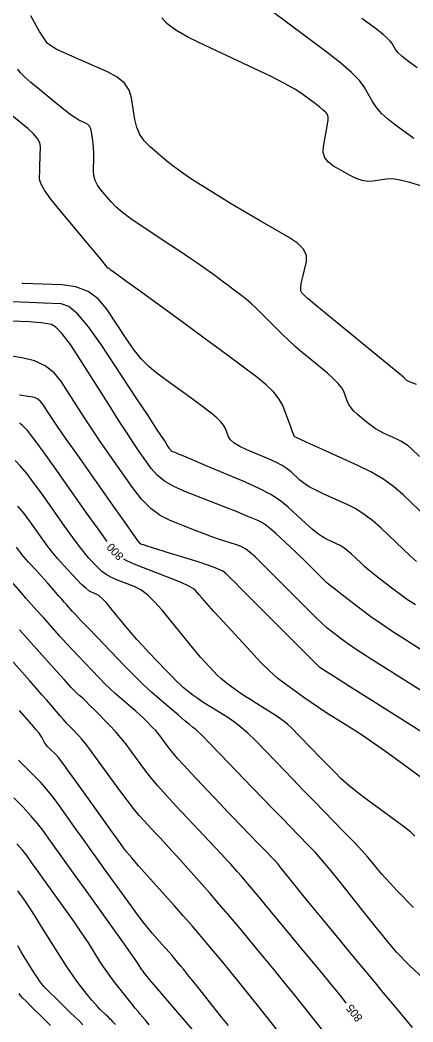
# Model space of a CAD drawing. Extents: x 2082232 to 2083549, y 592624 to 593832.
# Drawn here: x 2082379.6 to 2082413.2, y 593225.4 to 593311.1 of the extents above; entities that cross this region are included whole.
import ezdxf

# ---------------------------------------------------------------- set-up
doc = ezdxf.new("R2010")
doc.units = 0
doc.layers.add('DT_X_Contour_Major', color=7, linetype='Continuous')
doc.layers.add('DT_X_Contour_Minor', color=7, linetype='Continuous')

msp = doc.modelspace()

# ---------------------------------------------------------------- linework, layer by layer
at = {"layer": 'DT_X_Contour_Major'}
for points in [[(2082413.299, 593300.988), (2082411.619, 593302.197), (2082411.032, 593302.655), (2082410.532, 593303.123), (2082410.12, 593303.6), (2082409.794, 593304.087), (2082409.042, 593305.398), (2082408.633, 593305.95), (2082407.967, 593306.623), (2082407.047, 593307.418), (2082405.871, 593308.333), (2082402.394, 593310.936), (2082401.153, 593311.846)], [(2082413.526, 593264.794), (2082413.013, 593265.267), (2082412.371, 593265.872), (2082410.486, 593267.66), (2082409.774, 593268.288), (2082409.053, 593268.833), (2082408.322, 593269.295), (2082407.582, 593269.673), (2082405.597, 593270.569), (2082404.91, 593270.896), (2082404.339, 593271.204), (2082403.883, 593271.495), (2082403.542, 593271.767), (2082402.788, 593272.469), (2082402.454, 593272.736), (2082402.019, 593273.01), (2082401.483, 593273.29), (2082400.845, 593273.577), (2082399.009, 593274.352), (2082398.394, 593274.64), (2082397.926, 593274.922), (2082397.604, 593275.2), (2082397.43, 593275.472), (2082397.159, 593276.191), (2082397.015, 593276.469), (2082396.786, 593276.762), (2082396.471, 593277.071), (2082396.071, 593277.395), (2082394.889, 593278.281), (2082394.426, 593278.626), (2082393.925, 593278.996), (2082393.385, 593279.392), (2082392.806, 593279.813), (2082391.21, 593280.969), (2082390.606, 593281.471), (2082389.99, 593282.108), (2082389.363, 593282.881), (2082388.723, 593283.79), (2082387.004, 593286.396), (2082386.282, 593287.257), (2082385.405, 593287.887), (2082384.374, 593288.285), (2082383.189, 593288.451), (2082379.821, 593288.586), (2082379.741, 593288.589)], [(2082387.036, 593266.525), (2082386.957, 593266.632), (2082386.26, 593267.6), (2082385.342, 593268.893), (2082382.599, 593272.777), (2082381.68, 593274.07), (2082380.978, 593275.038), (2082380.495, 593275.679), (2082380.229, 593275.995), (2082379.812, 593276.404), (2082379.667, 593276.547), (2082379.545, 593276.672)], [(2082415.223, 593245.361), (2082412.001, 593247.717), (2082410.86, 593248.544), (2082409.851, 593249.256), (2082408.976, 593249.854), (2082408.234, 593250.339), (2082406.433, 593251.478), (2082405.767, 593251.905), (2082405.121, 593252.331), (2082404.495, 593252.757), (2082403.888, 593253.183), (2082402.296, 593254.318), (2082401.663, 593254.811), (2082400.958, 593255.439), (2082400.181, 593256.202), (2082399.332, 593257.1), (2082396.971, 593259.675), (2082396.181, 593260.539), (2082395.581, 593261.2), (2082395.171, 593261.658), (2082394.951, 593261.913), (2082394.617, 593262.322), (2082394.395, 593262.499), (2082393.979, 593262.726), (2082393.369, 593263.002), (2082392.565, 593263.326), (2082390.162, 593264.256), (2082389.355, 593264.58), (2082388.738, 593264.856), (2082388.457, 593265.005)], [(2082407.511, 593227.044), (2082407.201, 593227.434), (2082406.728, 593228.022), (2082406.054, 593228.847), (2082405.177, 593229.909), (2082404.099, 593231.208), (2082400.956, 593234.989), (2082399.899, 593236.259), (2082399.083, 593237.233), (2082398.51, 593237.91), (2082398.179, 593238.292), (2082397.62, 593238.915), (2082397.323, 593239.24), (2082396.852, 593239.747), (2082396.205, 593240.437), (2082395.384, 593241.309), (2082392.96, 593243.879), (2082392.111, 593244.797), (2082391.379, 593245.623), (2082390.766, 593246.358), (2082390.272, 593247.002), (2082389.11, 593248.597), (2082388.668, 593249.182), (2082388.214, 593249.739), (2082387.748, 593250.27), (2082387.269, 593250.774), (2082385.976, 593252.082), (2082385.542, 593252.52), (2082385.208, 593252.852), (2082384.976, 593253.079), (2082384.844, 593253.201), (2082384.626, 593253.385), (2082384.541, 593253.459), (2082384.451, 593253.544), (2082384.354, 593253.638), (2082384.251, 593253.743), (2082383.97, 593254.036), (2082383.764, 593254.258), (2082383.359, 593254.704), (2082382.754, 593255.374), (2082381.949, 593256.269), (2082379.537, 593258.954)], [(2082390.634, 593225.193), (2082390.303, 593225.603), (2082389.873, 593226.102), (2082389.686, 593226.324), (2082389.446, 593226.616), (2082389.154, 593226.977), (2082388.809, 593227.409), (2082387.818, 593228.654), (2082387.451, 593229.13), (2082387.092, 593229.624), (2082386.741, 593230.135), (2082386.398, 593230.664), (2082385.494, 593232.097), (2082385.129, 593232.663), (2082384.713, 593233.283), (2082384.246, 593233.958), (2082383.727, 593234.688), (2082382.276, 593236.708), (2082381.77, 593237.411), (2082381.343, 593238.006), (2082380.995, 593238.492), (2082380.724, 593238.87), (2082380.108, 593239.734), (2082379.795, 593240.126), (2082379.318, 593240.654)]]:
    msp.add_lwpolyline(points, dxfattribs=at)
at = {"layer": 'DT_X_Contour_Minor'}
for points in [[(2082413.513, 593279.946), (2082413.075, 593280.124), (2082412.802, 593280.24), (2082412.693, 593280.294), (2082412.622, 593280.353), (2082412.599, 593280.374), (2082412.581, 593280.391), (2082412.569, 593280.405), (2082412.563, 593280.415), (2082412.554, 593280.437), (2082412.396, 593280.572), (2082411.925, 593280.961), (2082411.144, 593281.602), (2082410.051, 593282.497), (2082406.721, 593285.22), (2082405.614, 593286.128), (2082404.792, 593286.807), (2082404.255, 593287.259), (2082404.002, 593287.483), (2082403.707, 593287.777), (2082403.626, 593287.939), (2082403.607, 593288.205), (2082403.648, 593288.575), (2082403.75, 593289.049), (2082404.104, 593290.452), (2082404.107, 593290.977), (2082403.851, 593291.501), (2082403.336, 593292.023), (2082402.561, 593292.544), (2082400.15, 593293.931), (2082399.265, 593294.445), (2082398.416, 593294.945), (2082397.604, 593295.433), (2082396.828, 593295.907), (2082394.81, 593297.156), (2082394.079, 593297.624), (2082393.399, 593298.091), (2082392.77, 593298.558), (2082392.193, 593299.024), (2082390.723, 593300.266), (2082390.227, 593300.761), (2082389.844, 593301.314), (2082389.573, 593301.926), (2082389.414, 593302.596), (2082389.14, 593304.46), (2082388.933, 593305.123), (2082388.519, 593305.713), (2082387.898, 593306.231), (2082387.069, 593306.676), (2082384.581, 593307.765), (2082383.749, 593308.133), (2082383.116, 593308.42), (2082382.683, 593308.626), (2082382.45, 593308.752), (2082382.095, 593308.977), (2082381.943, 593309.113), (2082381.753, 593309.352), (2082381.526, 593309.694), (2082381.262, 593310.139), (2082380.507, 593311.462)], [(2082413.895, 593296.918), (2082412.935, 593297.225), (2082412.125, 593297.425), (2082411.463, 593297.518), (2082410.951, 593297.505), (2082409.784, 593297.329), (2082409.334, 593297.309), (2082408.861, 593297.381), (2082408.365, 593297.545), (2082407.846, 593297.802), (2082406.429, 593298.61), (2082405.976, 593298.943), (2082405.681, 593299.333), (2082405.544, 593299.782), (2082405.564, 593300.289), (2082405.829, 593301.72), (2082405.91, 593302.198), (2082405.957, 593302.561), (2082405.967, 593302.808), (2082405.943, 593302.94), (2082405.83, 593303.137), (2082405.738, 593303.242), (2082405.545, 593303.413), (2082405.253, 593303.647), (2082404.861, 593303.946), (2082403.681, 593304.829), (2082403.097, 593305.211), (2082402.228, 593305.693), (2082401.075, 593306.277), (2082399.637, 593306.961), (2082395.425, 593308.921), (2082394.009, 593309.621), (2082392.921, 593310.252), (2082392.16, 593310.814), (2082391.728, 593311.306)], [(2082413.577, 593307.027), (2082412.849, 593307.565), (2082412.297, 593308.004), (2082411.922, 593308.344), (2082411.724, 593308.585), (2082411.431, 593309.096), (2082411.271, 593309.311), (2082411.012, 593309.573), (2082410.654, 593309.882), (2082410.196, 593310.238), (2082408.842, 593311.252)], [(2082413.778, 593273.792), (2082413.088, 593274.447), (2082412.813, 593274.684), (2082412.505, 593274.903), (2082412.165, 593275.105), (2082411.792, 593275.289), (2082410.755, 593275.757), (2082410.375, 593275.945), (2082410.01, 593276.157), (2082409.662, 593276.394), (2082409.33, 593276.656), (2082408.467, 593277.387), (2082408.17, 593277.664), (2082407.925, 593277.948), (2082407.733, 593278.238), (2082407.594, 593278.535), (2082407.292, 593279.336), (2082407.12, 593279.658), (2082406.829, 593280.026), (2082406.418, 593280.44), (2082405.89, 593280.898), (2082404.321, 593282.181), (2082403.733, 593282.675), (2082403.145, 593283.195), (2082402.558, 593283.74), (2082401.971, 593284.311), (2082400.406, 593285.867), (2082399.851, 593286.409), (2082399.361, 593286.866), (2082398.935, 593287.239), (2082398.574, 593287.528), (2082397.696, 593288.187), (2082397.358, 593288.438), (2082397.004, 593288.7), (2082396.634, 593288.971), (2082396.248, 593289.252), (2082395.197, 593290.014), (2082394.732, 593290.342), (2082394.127, 593290.756), (2082393.382, 593291.256), (2082392.497, 593291.841), (2082389.95, 593293.515), (2082389.073, 593294.113), (2082388.352, 593294.652), (2082387.789, 593295.132), (2082387.382, 593295.554), (2082386.507, 593296.599), (2082386.221, 593296.995), (2082386.019, 593297.399), (2082385.901, 593297.811), (2082385.868, 593298.231), (2082385.89, 593299.363), (2082385.893, 593299.77), (2082385.882, 593300.143), (2082385.859, 593300.48), (2082385.823, 593300.783), (2082385.711, 593301.545), (2082385.648, 593301.807), (2082385.542, 593302.021), (2082385.392, 593302.187), (2082385.2, 593302.304), (2082384.63, 593302.554), (2082384.36, 593302.704), (2082383.977, 593302.966), (2082383.482, 593303.34), (2082382.874, 593303.826), (2082381.103, 593305.272), (2082380.497, 593305.78), (2082380.009, 593306.221), (2082379.638, 593306.595), (2082379.384, 593306.901)], [(2082414.428, 593268.549), (2082412.367, 593270.503), (2082411.545, 593271.21), (2082410.627, 593271.865), (2082409.612, 593272.467), (2082408.499, 593273.017), (2082405.404, 593274.414), (2082404.388, 593274.872), (2082403.662, 593275.2), (2082403.225, 593275.398), (2082403.079, 593275.464), (2082403.074, 593275.468), (2082403.071, 593275.473), (2082403.066, 593275.484), (2082403.059, 593275.501), (2082403.05, 593275.525), (2082403.024, 593275.596), (2082402.99, 593275.686), (2082402.908, 593275.902), (2082402.78, 593276.246), (2082402.069, 593278.137), (2082401.778, 593278.69), (2082401.307, 593279.283), (2082400.656, 593279.915), (2082399.824, 593280.587), (2082397.364, 593282.43), (2082396.402, 593283.148), (2082395.358, 593283.918), (2082394.234, 593284.742), (2082393.029, 593285.618), (2082389.707, 593288.025), (2082388.617, 593288.816), (2082387.836, 593289.384), (2082387.364, 593289.729), (2082387.203, 593289.851), (2082387.184, 593289.879), (2082387.176, 593289.888), (2082387.165, 593289.895), (2082387.151, 593289.9), (2082387.135, 593289.902), (2082387.088, 593289.903), (2082387.072, 593289.906), (2082387.061, 593289.913), (2082387.054, 593289.924), (2082387.051, 593289.938), (2082387.05, 593289.983), (2082386.94, 593290.127), (2082386.614, 593290.527), (2082386.07, 593291.182), (2082385.31, 593292.092), (2082382.991, 593294.86), (2082382.231, 593295.805), (2082381.69, 593296.562), (2082381.367, 593297.132), (2082381.264, 593297.515), (2082381.279, 593298.287), (2082381.286, 593298.579), (2082381.294, 593298.875), (2082381.304, 593299.175), (2082381.316, 593299.479), (2082381.35, 593300.296), (2082381.29, 593300.622), (2082381.086, 593300.986), (2082380.738, 593301.389), (2082380.246, 593301.83), (2082378.741, 593303.059)], [(2082413.424, 593261.087), (2082412.759, 593261.533), (2082412.165, 593261.951), (2082411.641, 593262.342), (2082410.337, 593263.347), (2082409.871, 593263.712), (2082409.451, 593264.057), (2082409.077, 593264.379), (2082408.748, 593264.68), (2082407.934, 593265.452), (2082407.626, 593265.724), (2082407.314, 593265.96), (2082406.998, 593266.159), (2082406.679, 593266.323), (2082405.82, 593266.71), (2082405.468, 593266.903), (2082405.054, 593267.192), (2082404.579, 593267.576), (2082404.042, 593268.056), (2082402.529, 593269.464), (2082401.876, 593269.993), (2082401.049, 593270.522), (2082400.051, 593271.052), (2082398.879, 593271.582), (2082395.525, 593272.997), (2082394.416, 593273.465), (2082393.603, 593273.807), (2082393.086, 593274.024), (2082392.867, 593274.115), (2082392.675, 593274.19), (2082392.609, 593274.219), (2082392.554, 593274.251), (2082392.51, 593274.286), (2082392.477, 593274.324), (2082392.403, 593274.429), (2082392.369, 593274.479), (2082392.321, 593274.552), (2082392.26, 593274.647), (2082392.185, 593274.765), (2082391.967, 593275.11), (2082391.754, 593275.437), (2082391.278, 593276.161), (2082390.54, 593277.281), (2082389.54, 593278.797), (2082386.522, 593283.37), (2082385.46, 593284.874), (2082384.538, 593285.954), (2082383.756, 593286.611), (2082383.115, 593286.846), (2082381.591, 593286.907), (2082380.99, 593286.93), (2082380.331, 593286.953), (2082379.613, 593286.977), (2082378.837, 593287.001)], [(2082415.985, 593255.953), (2082412.673, 593258.048), (2082411.505, 593258.797), (2082410.488, 593259.474), (2082409.621, 593260.078), (2082408.904, 593260.609), (2082407.191, 593261.929), (2082406.615, 593262.377), (2082406.171, 593262.729), (2082405.858, 593262.987), (2082405.677, 593263.15), (2082405.37, 593263.458), (2082405.241, 593263.587), (2082405.084, 593263.744), (2082404.898, 593263.929), (2082404.685, 593264.143), (2082404.077, 593264.748), (2082403.82, 593265), (2082403.506, 593265.302), (2082403.134, 593265.654), (2082402.705, 593266.055), (2082401.484, 593267.192), (2082401.043, 593267.582), (2082400.638, 593267.899), (2082400.269, 593268.142), (2082399.935, 593268.312), (2082399.093, 593268.667), (2082398.688, 593268.834), (2082398.107, 593269.068), (2082397.349, 593269.368), (2082396.413, 593269.736), (2082393.684, 593270.805), (2082392.739, 593271.226), (2082391.951, 593271.687), (2082391.32, 593272.187), (2082390.847, 593272.728), (2082389.796, 593274.222), (2082389.336, 593274.893), (2082388.747, 593275.785), (2082388.027, 593276.899), (2082387.177, 593278.234), (2082384.737, 593282.09), (2082383.896, 593283.362), (2082383.204, 593284.283), (2082382.661, 593284.856), (2082382.267, 593285.079), (2082381.415, 593285.207), (2082381.001, 593285.254), (2082380.397, 593285.296), (2082379.604, 593285.335), (2082378.622, 593285.369)], [(2082415.756, 593252.593), (2082411.186, 593255.482), (2082409.645, 593256.463), (2082408.45, 593257.235), (2082407.601, 593257.801), (2082407.098, 593258.159), (2082406.217, 593258.838), (2082405.854, 593259.135), (2082405.424, 593259.519), (2082404.927, 593259.988), (2082404.364, 593260.544), (2082402.772, 593262.14), (2082402.2, 593262.714), (2082401.678, 593263.237), (2082401.205, 593263.71), (2082400.782, 593264.132), (2082399.72, 593265.19), (2082399.32, 593265.554), (2082398.919, 593265.849), (2082398.515, 593266.077), (2082398.108, 593266.237), (2082397.022, 593266.574), (2082396.563, 593266.725), (2082396, 593266.925), (2082395.335, 593267.173), (2082394.567, 593267.47), (2082392.38, 593268.326), (2082391.567, 593268.742), (2082390.769, 593269.348), (2082389.986, 593270.145), (2082389.218, 593271.131), (2082387.188, 593274.015), (2082386.454, 593275.068), (2082385.776, 593276.065), (2082385.151, 593277.005), (2082384.582, 593277.89), (2082383.137, 593280.173), (2082382.519, 593280.944), (2082381.75, 593281.544), (2082380.828, 593281.973), (2082379.755, 593282.232), (2082376.69, 593282.695)], [(2082415.527, 593249.232), (2082409.699, 593252.917), (2082407.784, 593254.128), (2082406.412, 593254.997), (2082405.581, 593255.524), (2082405.292, 593255.709), (2082405.244, 593255.746), (2082405.093, 593255.893), (2082404.677, 593256.308), (2082403.996, 593256.989), (2082403.05, 593257.938), (2082400.173, 593260.823), (2082399.208, 593261.792), (2082398.469, 593262.532), (2082397.957, 593263.045), (2082397.671, 593263.331), (2082397.212, 593263.789), (2082396.933, 593263.979), (2082396.443, 593264.205), (2082395.74, 593264.468), (2082394.825, 593264.766), (2082392.103, 593265.611), (2082391.206, 593265.89), (2082390.556, 593266.092), (2082390.153, 593266.219), (2082389.997, 593266.27), (2082389.909, 593266.304), (2082389.74, 593266.515), (2082389.296, 593267.124), (2082388.579, 593268.131), (2082387.588, 593269.534), (2082384.58, 593273.808), (2082383.572, 593275.243), (2082382.804, 593276.344), (2082382.276, 593277.112), (2082381.988, 593277.545), (2082381.538, 593278.256), (2082381.346, 593278.495), (2082381.106, 593278.682), (2082380.82, 593278.816), (2082380.486, 593278.896), (2082379.532, 593279.04)], [(2082413.385, 593241.315), (2082412.994, 593241.673), (2082412.409, 593242.143), (2082411.632, 593242.726), (2082409.302, 593244.43), (2082408.472, 593245.056), (2082407.731, 593245.655), (2082407.079, 593246.228), (2082406.516, 593246.775), (2082405.131, 593248.197), (2082404.642, 593248.699), (2082404.213, 593249.14), (2082403.844, 593249.519), (2082403.536, 593249.837), (2082402.793, 593250.603), (2082402.485, 593250.894), (2082402.118, 593251.192), (2082401.692, 593251.498), (2082401.207, 593251.812), (2082399.834, 593252.659), (2082399.345, 593252.964), (2082398.909, 593253.244), (2082398.525, 593253.499), (2082398.193, 593253.729), (2082397.378, 593254.31), (2082397.073, 593254.541), (2082396.771, 593254.799), (2082396.472, 593255.082), (2082396.175, 593255.392), (2082395.385, 593256.252), (2082395.045, 593256.635), (2082394.615, 593257.137), (2082394.096, 593257.76), (2082393.488, 593258.501), (2082391.746, 593260.639), (2082391.108, 593261.366), (2082390.498, 593261.946), (2082389.916, 593262.377), (2082389.363, 593262.659), (2082387.926, 593263.215), (2082387.418, 593263.437), (2082386.971, 593263.685), (2082386.585, 593263.96), (2082386.26, 593264.262), (2082385.475, 593265.101), (2082385.127, 593265.505), (2082384.671, 593266.088), (2082384.106, 593266.849), (2082383.434, 593267.788), (2082381.497, 593270.531), (2082380.806, 593271.485), (2082380.186, 593272.29), (2082379.638, 593272.946), (2082379.16, 593273.453)], [(2082413.276, 593235.22), (2082411.821, 593236.71), (2082411.316, 593237.234), (2082410.891, 593237.69), (2082410.545, 593238.077), (2082410.28, 593238.395), (2082409.68, 593239.151), (2082409.363, 593239.523), (2082408.861, 593240.072), (2082408.174, 593240.797), (2082407.302, 593241.699), (2082404.731, 593244.339), (2082403.805, 593245.29), (2082402.958, 593246.161), (2082402.189, 593246.952), (2082401.497, 593247.665), (2082399.758, 593249.459), (2082399.113, 593250.093), (2082398.485, 593250.65), (2082397.871, 593251.129), (2082397.274, 593251.531), (2082395.702, 593252.501), (2082395.16, 593252.841), (2082394.714, 593253.133), (2082394.364, 593253.379), (2082394.11, 593253.577), (2082393.56, 593254.041), (2082393.312, 593254.264), (2082392.98, 593254.584), (2082392.565, 593255.002), (2082392.065, 593255.516), (2082390.621, 593257.017), (2082390.091, 593257.579), (2082389.582, 593258.139), (2082389.096, 593258.699), (2082388.631, 593259.256), (2082387.421, 593260.742), (2082387.002, 593261.238), (2082386.652, 593261.611), (2082386.372, 593261.863), (2082386.161, 593261.992), (2082385.691, 593262.174), (2082385.481, 593262.293), (2082385.204, 593262.514), (2082384.86, 593262.837), (2082384.449, 593263.262), (2082383.264, 593264.53), (2082382.822, 593265.021), (2082382.385, 593265.544), (2082381.953, 593266.097), (2082381.526, 593266.683), (2082380.394, 593268.285), (2082379.932, 593268.9), (2082379.394, 593269.542)], [(2082414.089, 593229.173), (2082412.925, 593230.269), (2082412.511, 593230.668), (2082412.14, 593231.043), (2082411.813, 593231.395), (2082411.53, 593231.724), (2082410.833, 593232.568), (2082410.513, 593232.96), (2082410.076, 593233.503), (2082409.521, 593234.198), (2082408.849, 593235.044), (2082406.9, 593237.501), (2082406.187, 593238.383), (2082405.509, 593239.185), (2082404.867, 593239.909), (2082404.26, 593240.553), (2082402.69, 593242.166), (2082402.046, 593242.828), (2082401.293, 593243.603), (2082400.431, 593244.491), (2082399.459, 593245.492), (2082396.723, 593248.315), (2082395.819, 593249.244), (2082395.162, 593249.915), (2082394.751, 593250.328), (2082394.586, 593250.483), (2082394.473, 593250.553), (2082394.359, 593250.641), (2082394.1, 593250.854), (2082393.696, 593251.191), (2082393.148, 593251.654), (2082391.494, 593253.052), (2082390.842, 593253.625), (2082390.126, 593254.293), (2082389.348, 593255.057), (2082388.506, 593255.917), (2082386.177, 593258.338), (2082385.39, 593259.158), (2082384.775, 593259.802), (2082384.332, 593260.271), (2082384.061, 593260.565), (2082383.568, 593261.114), (2082383.372, 593261.333), (2082383.155, 593261.578), (2082382.915, 593261.85), (2082382.654, 593262.149), (2082381.928, 593262.98), (2082381.662, 593263.283), (2082381.406, 593263.57), (2082381.161, 593263.839), (2082380.928, 593264.092), (2082380.319, 593264.743), (2082380.104, 593264.978), (2082379.916, 593265.196), (2082379.754, 593265.395), (2082379.618, 593265.577), (2082379.292, 593266.039)], [(2082413.174, 593224.947), (2082412.087, 593226.255), (2082411.309, 593227.19), (2082410.84, 593227.753), (2082410.68, 593227.944), (2082410.666, 593227.957), (2082410.526, 593228.126), (2082410.115, 593228.623), (2082409.435, 593229.447), (2082408.484, 593230.599), (2082405.587, 593234.107), (2082404.604, 593235.301), (2082403.826, 593236.248), (2082403.252, 593236.951), (2082402.885, 593237.408), (2082402.177, 593238.3), (2082401.918, 593238.62), (2082401.672, 593238.911), (2082401.439, 593239.174), (2082401.219, 593239.408), (2082400.649, 593239.993), (2082400.412, 593240.237), (2082400.127, 593240.53), (2082399.795, 593240.872), (2082399.416, 593241.263), (2082398.342, 593242.37), (2082397.902, 593242.827), (2082397.385, 593243.368), (2082396.792, 593243.992), (2082396.124, 593244.699), (2082394.239, 593246.698), (2082393.594, 593247.389), (2082393.074, 593247.965), (2082392.679, 593248.426), (2082392.407, 593248.77), (2082391.85, 593249.536), (2082391.638, 593249.817), (2082391.42, 593250.084), (2082391.196, 593250.339), (2082390.966, 593250.581), (2082390.346, 593251.209), (2082390.095, 593251.455), (2082389.807, 593251.722), (2082389.484, 593252.01), (2082389.124, 593252.319), (2082388.114, 593253.172), (2082387.722, 593253.516), (2082387.302, 593253.907), (2082386.854, 593254.345), (2082386.379, 593254.83), (2082385.074, 593256.187), (2082384.577, 593256.708), (2082384.067, 593257.253), (2082383.543, 593257.823), (2082383.005, 593258.417), (2082381.553, 593260.034), (2082381.027, 593260.621), (2082380.539, 593261.168), (2082380.09, 593261.677), (2082379.678, 593262.146), (2082378.632, 593263.344)], [(2082405.717, 593224.417), (2082403.721, 593226.933), (2082402.959, 593227.887), (2082402.172, 593228.862), (2082401.358, 593229.857), (2082400.517, 593230.873), (2082398.242, 593233.61), (2082397.408, 593234.605), (2082396.614, 593235.538), (2082395.858, 593236.408), (2082395.142, 593237.216), (2082393.283, 593239.286), (2082392.628, 593240.014), (2082392.056, 593240.644), (2082391.567, 593241.177), (2082391.161, 593241.612), (2082390.189, 593242.643), (2082389.787, 593243.094), (2082389.311, 593243.677), (2082388.761, 593244.39), (2082388.136, 593245.234), (2082386.37, 593247.658), (2082385.764, 593248.481), (2082385.27, 593249.13), (2082384.888, 593249.606), (2082384.618, 593249.909), (2082384.047, 593250.487), (2082383.822, 593250.72), (2082383.575, 593250.986), (2082383.307, 593251.285), (2082383.016, 593251.617), (2082382.212, 593252.546), (2082381.873, 593252.935), (2082381.461, 593253.406), (2082380.975, 593253.96), (2082380.416, 593254.595), (2082378.826, 593256.398)], [(2082403.242, 593222.649), (2082400.241, 593226.432), (2082399.191, 593227.752), (2082398.29, 593228.877), (2082397.538, 593229.806), (2082396.935, 593230.538), (2082395.528, 593232.231), (2082394.96, 593232.905), (2082394.311, 593233.657), (2082393.582, 593234.487), (2082392.773, 593235.395), (2082390.506, 593237.92), (2082389.74, 593238.779), (2082389.143, 593239.464), (2082388.713, 593239.973), (2082388.452, 593240.307), (2082387.979, 593240.965), (2082387.737, 593241.303), (2082387.365, 593241.823), (2082386.864, 593242.525), (2082386.232, 593243.409), (2082384.376, 593246.008), (2082383.744, 593246.884), (2082383.241, 593247.561), (2082382.865, 593248.038), (2082382.618, 593248.317), (2082382.131, 593248.795), (2082381.963, 593248.967), (2082381.827, 593249.124), (2082381.723, 593249.266), (2082381.649, 593249.393), (2082381.495, 593249.711), (2082381.396, 593249.872), (2082381.213, 593250.116), (2082380.947, 593250.444), (2082380.597, 593250.854), (2082379.553, 593252.06)], [(2082397.42, 593225.128), (2082396.869, 593225.802), (2082396.32, 593226.487), (2082394.856, 593228.333), (2082394.35, 593228.969), (2082393.931, 593229.492), (2082393.599, 593229.904), (2082393.353, 593230.203), (2082392.814, 593230.852), (2082392.596, 593231.111), (2082392.347, 593231.399), (2082392.068, 593231.717), (2082391.758, 593232.065), (2082390.889, 593233.033), (2082390.515, 593233.475), (2082390.043, 593234.074), (2082389.475, 593234.831), (2082388.81, 593235.745), (2082386.906, 593238.394), (2082386.214, 593239.357), (2082385.565, 593240.262), (2082384.959, 593241.108), (2082384.396, 593241.896), (2082382.953, 593243.917), (2082382.415, 593244.644), (2082381.882, 593245.308), (2082381.355, 593245.911), (2082380.833, 593246.451), (2082379.448, 593247.808)], [(2082394.315, 593224.825), (2082392.246, 593227.227), (2082391.554, 593228.032), (2082391.031, 593228.643), (2082390.676, 593229.061), (2082390.49, 593229.285), (2082390.218, 593229.627), (2082390.118, 593229.758), (2082390.019, 593229.893), (2082389.923, 593230.034), (2082389.828, 593230.179), (2082389.58, 593230.572), (2082389.385, 593230.86), (2082388.986, 593231.426), (2082388.383, 593232.272), (2082387.576, 593233.398), (2082385.151, 593236.771), (2082384.307, 593237.946), (2082383.594, 593238.939), (2082383.012, 593239.752), (2082382.56, 593240.383), (2082381.531, 593241.825), (2082381.086, 593242.404), (2082380.524, 593243.056), (2082379.844, 593243.783), (2082379.047, 593244.585)], [(2082387.75, 593225.203), (2082387.528, 593225.438), (2082387.43, 593225.54), (2082387.303, 593225.669), (2082387.146, 593225.824), (2082386.96, 593226.007), (2082386.425, 593226.53), (2082386.213, 593226.746), (2082385.982, 593227.002), (2082385.73, 593227.297), (2082385.457, 593227.633), (2082384.703, 593228.581), (2082384.382, 593229.009), (2082383.986, 593229.579), (2082383.515, 593230.292), (2082382.967, 593231.148), (2082381.408, 593233.622), (2082380.874, 593234.465), (2082380.441, 593235.139), (2082380.109, 593235.643), (2082379.879, 593235.978), (2082379.4, 593236.644)], [(2082384.962, 593225.179), (2082384.662, 593225.482), (2082384.293, 593225.848), (2082383.855, 593226.278), (2082382.593, 593227.509), (2082382.171, 593227.924), (2082381.85, 593228.244), (2082381.631, 593228.47), (2082381.513, 593228.602), (2082381.333, 593228.828), (2082381.241, 593228.955), (2082381.098, 593229.168), (2082380.904, 593229.467), (2082380.66, 593229.851), (2082379.943, 593230.989), (2082379.67, 593231.437), (2082379.387, 593231.93)], [(2082382.201, 593225.119), (2082381.845, 593225.476), (2082381.47, 593225.846), (2082380.444, 593226.848), (2082380.098, 593227.192), (2082379.828, 593227.475), (2082379.635, 593227.695), (2082379.519, 593227.853)]]:
    msp.add_lwpolyline(points, dxfattribs=at)

# ---------------------------------------------------------------- texts
at = {"layer": 'DT_X_Contour_Major'}
for s, rotation, p in [('800', 133.07542, (2082388.515, 593265.302)), ('805', 128.51333, (2082408.954, 593225.79))]:
    msp.add_text(s, height=0.7, rotation=rotation, dxfattribs=at).set_placement(p)

doc.saveas('drawing.dxf')
